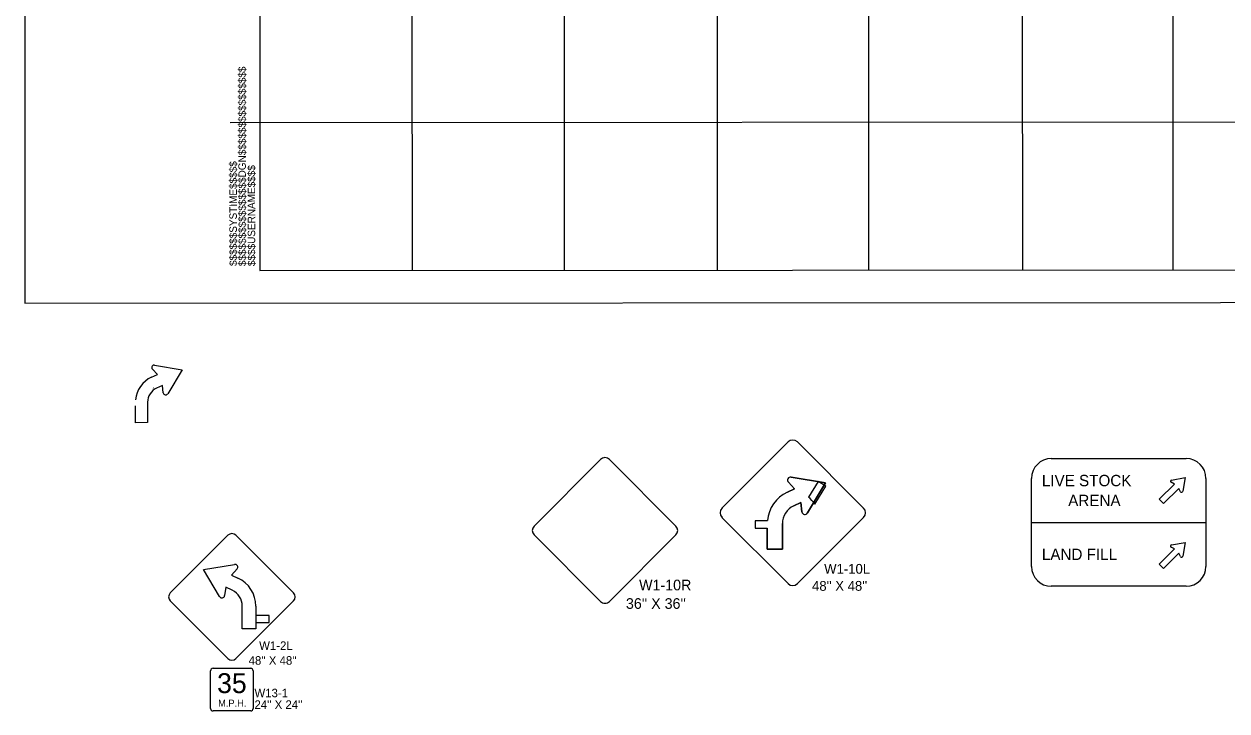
# Model space of a CAD drawing. Extents: x 1977705 to 1981198, y 827296 to 829291.
# Drawn here: x 1979337 to 1980184, y 827354 to 827837 of the extents above; entities that cross this region are included whole.
import ezdxf

# ---------------------------------------------------------------- set-up
doc = ezdxf.new("R2010")
doc.units = 0
for name, color, linetype in [('Default', 7, 'Continuous'), ('Level 19', 7, 'Continuous'), ('Level 22', 7, 'Continuous'), ('Level 23', 7, 'Continuous'), ('Level 3', 7, 'Continuous'), ('Level 34', 7, 'Continuous'), ('Level 5', 7, 'Continuous'), ('Level 7', 7, 'Continuous')]:
    doc.layers.add(name, color=color, linetype=linetype)

msp = doc.modelspace()

# ---------------------------------------------------------------- linework, layer by layer
at = {"layer": 'Default'}
for p, q in [((1979428.52, 827597.16), (1979447.93, 827593.88)), ((1979428.52, 827597.16), (1979428.52, 827597.16)), ((1979447.93, 827593.88), (1979437.81, 827576.99)), ((1979427.68, 827581.01), (1979427.66, 827581.03)), ((1979434.06, 827582.8), (1979429.99, 827580.94)), ((1979434.67, 827577.66), (1979434.06, 827582.8)), ((1979423.63, 827571), (1979423.63, 827556.62)), ((1979415.12, 827565.15), (1979415.12, 827568.47)), ((1979415.13, 827556.61), (1979415.12, 827565.15)), ((1979423.63, 827556.62), (1979415.13, 827556.61)), ((1979876.66, 827518.26), (1979876.66, 827518.25)), ((1979875.6, 827498.06), (1979875.58, 827498.09)), ((1979748.75, 827430.83), (1979795.6, 827477.68))]:
    msp.add_line(p, q, dxfattribs=at)
for points in [[(1979426.44, 827588.67), (1979430.5, 827590.52), (1979426.99, 827594.34)], [(1979742.56, 827530.71), (1979695.72, 827483.86)], [(1979795.6, 827483.86), (1979748.75, 827530.71)], [(1979695.72, 827477.68), (1979742.56, 827430.83)]]:
    msp.add_lwpolyline(points, dxfattribs=at)
for centre, radius, start, end in [((1979428.24, 827595.49), 1.7, 80.39954, 222.52148), ((1979434.57, 827571), 19.45, 114.72375, 175.10401), ((1979434.57, 827571), 10.94, 114.72375, 180.03077), ((1979436.36, 827577.86), 1.7, 186.91942, 329.04792), ((1979745.66, 827527.62), 4.38, 89.99348, 135), ((1979745.66, 827527.62), 4.38, 44.98697, 89.99348), ((1979698.81, 827480.77), 4.38, 135, 225), ((1979792.5, 827480.77), 4.38, 315, 45), ((1979745.66, 827433.92), 4.38, 225, 270), ((1979745.66, 827433.92), 4.38, 270, 315)]:
    msp.add_arc(centre, radius, start, end, dxfattribs=at)
at = {"layer": 'Level 19'}
for p, q in [((1979874.56, 827543.03), (1979828.03, 827496.5)), ((1979927.73, 827496.5), (1979881.2, 827543.03)), ((1979876.66, 827518.25), (1979876.66, 827518.26)), ((1979876.66, 827518.25), (1979876.66, 827518.26)), ((1979876.66, 827518.25), (1979900.92, 827514.16)), ((1979900.92, 827514.16), (1979876.66, 827518.25)), ((1979900.92, 827514.16), (1979876.66, 827518.25)), ((1979879.13, 827509.96), (1979874.05, 827507.64)), ((1979874.74, 827514.73), (1979879.13, 827509.96)), ((1979900.92, 827514.16), (1979888.27, 827493.04)), ((1979888.27, 827493.04), (1979900.92, 827514.16)), ((1979888.27, 827493.04), (1979900.92, 827514.16)), ((1979883.58, 827500.31), (1979878.5, 827497.98)), ((1979878.5, 827497.98), (1979883.58, 827500.31)), ((1979878.5, 827497.98), (1979883.58, 827500.31)), ((1979884.34, 827493.88), (1979883.58, 827500.31)), ((1979883.58, 827500.31), (1979884.34, 827493.88)), ((1979883.58, 827500.31), (1979884.34, 827493.88)), ((1979828.03, 827489.86), (1979874.56, 827443.34)), ((1979870.54, 827485.55), (1979870.55, 827467.58)), ((1979870.55, 827467.58), (1979870.54, 827485.55)), ((1979870.55, 827467.58), (1979870.54, 827485.55)), ((1979881.2, 827443.34), (1979927.73, 827489.86)), ((1979480.08, 827477.34), (1979439.62, 827436.87)), ((1979526.32, 827436.87), (1979485.85, 827477.34)), ((1979859.91, 827478.25), (1979859.91, 827482.39)), ((1979859.91, 827482.39), (1979859.91, 827478.25)), ((1979859.91, 827482.39), (1979859.91, 827478.25)), ((1979859.92, 827467.57), (1979859.91, 827478.25)), ((1979859.91, 827478.25), (1979859.92, 827467.57)), ((1979859.91, 827478.25), (1979859.92, 827467.57)), ((1979870.55, 827467.58), (1979859.92, 827467.57)), ((1979859.92, 827467.57), (1979870.55, 827467.58)), ((1979859.92, 827467.57), (1979870.55, 827467.58)), ((1979439.62, 827431.1), (1979480.08, 827390.63)), ((1979485.85, 827390.63), (1979526.32, 827431.1)), ((1979490.29, 827411.44), (1979490.29, 827427.5)), ((1979490.29, 827411.44), (1979490.29, 827427.5)), ((1979490.29, 827411.44), (1979490.29, 827427.5)), ((1979499.81, 827421), (1979499.8, 827416.05)), ((1979497.97, 827381.96), (1979497.97, 827355.46))]:
    msp.add_line(p, q, dxfattribs=at)
for points in [[(1979874.05, 827507.64), (1979879.13, 827509.96), (1979874.74, 827514.73)], [(1979874.74, 827514.73), (1979879.13, 827509.96), (1979874.05, 827507.64)], [(1979893.28, 827499.25), (1979901.05, 827511.91), (1979895.71, 827515.18), (1979889.02, 827504.27)], [(1979860, 827487.63), (1979851.39, 827487.63), (1979851.39, 827482.39), (1979859.91, 827482.39)], [(1979860, 827487.63), (1979851.39, 827487.63), (1979851.39, 827482.39), (1979859.91, 827482.39)], [(1979860, 827487.63), (1979851.39, 827487.63), (1979851.39, 827482.39), (1979859.91, 827482.39)], [(1979474.35, 827434.16), (1979463.08, 827453.21), (1979484.91, 827456.87)], [(1979474.35, 827434.16), (1979463.08, 827453.21), (1979484.91, 827456.87)], [(1979474.35, 827434.16), (1979463.08, 827453.21), (1979484.91, 827456.87)], [(1979486.63, 827453.7), (1979482.65, 827449.36), (1979487.22, 827447.23)], [(1979486.63, 827453.7), (1979482.65, 827449.36), (1979487.22, 827447.23)], [(1979486.63, 827453.7), (1979482.65, 827449.36), (1979487.22, 827447.23)], [(1979483.21, 827438.6), (1979478.63, 827440.72), (1979477.88, 827434.89)], [(1979483.21, 827438.6), (1979478.63, 827440.72), (1979477.88, 827434.89)], [(1979483.21, 827438.6), (1979478.63, 827440.72), (1979477.88, 827434.89)], [(1979499.81, 827427.5), (1979499.81, 827411.44), (1979490.29, 827411.44)], [(1979499.81, 827427.5), (1979499.81, 827411.44), (1979490.29, 827411.44)], [(1979499.81, 827427.5), (1979499.81, 827411.44), (1979490.29, 827411.44)], [(1979499.8, 827416.05), (1979509.17, 827416.05), (1979509.17, 827421), (1979499.81, 827421)], [(1979469.72, 827383.71), (1979482.97, 827383.71)], [(1979482.97, 827383.71), (1979496.22, 827383.71)], [(1979467.97, 827355.46), (1979467.97, 827381.96)], [(1979482.97, 827353.71), (1979469.72, 827353.71)], [(1979496.22, 827353.71), (1979482.97, 827353.71)]]:
    msp.add_lwpolyline(points, dxfattribs=at)
for centre, radius, start, end in [((1979877.88, 827539.71), 4.69, 45, 135), ((1979876.3, 827516.17), 2.12, 80.39954, 222.52148), ((1979876.3, 827516.17), 2.12, 80.39954, 222.52148), ((1979876.3, 827516.17), 2.12, 80.39954, 222.52148), ((1979884.22, 827485.56), 24.31, 114.72375, 175.10401), ((1979884.22, 827485.56), 24.31, 114.72375, 175.10401), ((1979884.22, 827485.56), 24.31, 114.72375, 175.10401), ((1979872.22, 827485.72), 25.03, 32.7091, 47.83665), ((1979831.35, 827493.18), 4.69, 135, 225), ((1979884.22, 827485.56), 13.68, 114.72375, 180.03077), ((1979884.22, 827485.56), 13.68, 114.72375, 180.03077), ((1979884.22, 827485.56), 13.68, 114.72375, 180.03077), ((1979886.45, 827494.13), 2.12, 186.91942, 329.04792), ((1979886.45, 827494.13), 2.12, 186.91942, 329.04792), ((1979886.45, 827494.13), 2.12, 186.91942, 329.04792), ((1979924.41, 827493.18), 4.69, 315, 45), ((1979482.97, 827474.45), 4.08, 45, 135), ((1979877.88, 827446.65), 4.69, 225, 315), ((1979442.5, 827433.99), 4.08, 135, 225), ((1979523.43, 827433.99), 4.08, 315, 45), ((1979469.72, 827381.96), 1.75, 89.98697, 180), ((1979482.97, 827393.52), 4.08, 225, 315), ((1979496.22, 827381.96), 1.75, 0, 90), ((1979469.72, 827355.46), 1.75, 180, 270), ((1979496.22, 827355.46), 1.75, 270, 360)]:
    msp.add_arc(centre, radius, start, end, dxfattribs=at)
for centre, major_axis, start_param, end_param in [((1979485.23, 827454.99), (0, 1.9), 3.969953, 6.449197), ((1979485.23, 827454.99), (0, 1.9), 3.969953, 6.449197), ((1979485.23, 827454.99), (0, 1.9), 3.969953, 6.449197), ((1979478.05, 827427.5), (0, 21.77), 4.712389, 5.847944), ((1979478.05, 827427.5), (0, 21.77), 4.712389, 5.847944), ((1979478.05, 827427.5), (0, 21.77), 4.712389, 5.847944), ((1979475.99, 827435.13), (0, -1.9), 5.246691, 7.725935), ((1979475.99, 827435.13), (0, -1.9), 5.246691, 7.725935), ((1979475.99, 827435.13), (0, -1.9), 5.246691, 7.725935), ((1979478.05, 827427.5), (0, 12.24), 4.712389, 5.847944), ((1979478.05, 827427.5), (0, 12.24), 4.712389, 5.847944), ((1979478.05, 827427.5), (0, 12.24), 4.712389, 5.847944)]:
    msp.add_ellipse(centre, major_axis=major_axis, ratio=0.999989, start_param=start_param, end_param=end_param, dxfattribs=at)
at = {"layer": 'Level 22'}
msp.add_line((1980045.96, 827486.4), (1980168.72, 827486.4), dxfattribs=at)
for points in [[(1980059.89, 827531.35), (1980154.79, 827531.35)], [(1980045.96, 827455.39), (1980045.96, 827517.42)], [(1980168.72, 827517.42), (1980168.72, 827455.39)], [(1980154.79, 827441.45), (1980059.89, 827441.45)]]:
    msp.add_lwpolyline(points, dxfattribs=at)
for centre, start, end in [((1980059.89, 827517.42), 90, 180), ((1980154.79, 827517.42), 0, 90), ((1980059.89, 827455.39), 180, 270), ((1980154.79, 827455.39), 270, 0)]:
    msp.add_arc(centre, 13.93, start, end, dxfattribs=at)
at = {"layer": 'Level 23'}
for points in [[(1980144.44, 827516.24), (1980154.22, 827518.06), (1980152.39, 827508.28)], [(1980144.44, 827516.24), (1980154.22, 827518.06), (1980152.39, 827508.28)], [(1980144.44, 827516.24), (1980154.22, 827518.06), (1980152.39, 827508.28)], [(1980150.79, 827508.04), (1980149.57, 827510.39), (1980138.87, 827499.69), (1980135.84, 827502.71), (1980146.55, 827513.42), (1980144.2, 827514.63)], [(1980150.79, 827508.04), (1980149.57, 827510.39), (1980138.87, 827499.69), (1980135.84, 827502.71), (1980146.55, 827513.42), (1980144.2, 827514.63)], [(1980150.79, 827508.04), (1980149.57, 827510.39), (1980138.87, 827499.69), (1980135.84, 827502.71), (1980146.55, 827513.42), (1980144.2, 827514.63)], [(1980150.79, 827462.34), (1980149.57, 827464.69), (1980138.87, 827453.99), (1980135.84, 827457.01), (1980146.55, 827467.72), (1980144.2, 827468.94)], [(1980150.79, 827462.34), (1980149.57, 827464.69), (1980138.87, 827453.99), (1980135.84, 827457.01), (1980146.55, 827467.72), (1980144.2, 827468.94)], [(1980150.79, 827462.34), (1980149.57, 827464.69), (1980138.87, 827453.99), (1980135.84, 827457.01), (1980146.55, 827467.72), (1980144.2, 827468.94)], [(1980144.44, 827470.54), (1980154.22, 827472.36), (1980152.39, 827462.58)], [(1980144.44, 827470.54), (1980154.22, 827472.36), (1980152.39, 827462.58)], [(1980144.44, 827470.54), (1980154.22, 827472.36), (1980152.39, 827462.58)]]:
    msp.add_lwpolyline(points, dxfattribs=at)
for centre, start, end in [((1980144.59, 827515.39), 100.55076, 242.60096), ((1980144.59, 827515.39), 100.55076, 242.60096), ((1980144.59, 827515.39), 100.55076, 242.60096), ((1980151.55, 827508.43), 207.39904, 349.44924), ((1980151.55, 827508.43), 207.39904, 349.44924), ((1980151.55, 827508.43), 207.39904, 349.44924), ((1980144.59, 827469.7), 100.55076, 242.60096), ((1980144.59, 827469.7), 100.55076, 242.60096), ((1980144.59, 827469.7), 100.55076, 242.60096), ((1980151.55, 827462.74), 207.39904, 349.44924), ((1980151.55, 827462.74), 207.39904, 349.44924), ((1980151.55, 827462.74), 207.39904, 349.44924)]:
    msp.add_arc(centre, 0.856, start, end, dxfattribs=at)
at = {"layer": 'Level 3'}
msp.add_lwpolyline([(1981020.16, 828736.58), (1979336.66, 828735.68), (1979337.25, 827640.68), (1981020.75, 827641.58)], close=True, dxfattribs=at)
at = {"layer": 'Level 34'}
for p, q in [((1979610.04, 827663.85), (1979609.44, 828783.03)), ((1979824.92, 827663.96), (1979824.32, 828783.14)), ((1980039.8, 827664.08), (1980039.2, 828783.26)), ((1981002.3, 827768.54), (1979481.66, 827767.72))]:
    msp.add_line(p, q, dxfattribs=at)
at = {"layer": 'Level 7'}
msp.add_lwpolyline([(1981001.8, 828714.37), (1979502.12, 828713.56), (1979502.69, 827663.79), (1981002.36, 827664.6)], close=True, dxfattribs=at)
for points in [[(1979716.94, 828713.68), (1979716.94, 827663.9)], [(1979931.19, 828713.79), (1979931.19, 827664.02)], [(1980145.44, 828713.91), (1980145.44, 827664.13)]]:
    msp.add_lwpolyline(points, dxfattribs=at)

# ---------------------------------------------------------------- texts
at = {"layer": 'Default'}
for s, height, p in [('W1-10L', 6.899, (1979899.97, 827450.28)), ('W1-10R', 7.5, (1979769.67, 827438.59)), ("48'' X 48''", 6.8989, (1979891.44, 827438.29)), ("36'' X 36''", 7.5002, (1979760.4, 827425.56)), ('W1-2L', 6, (1979502.18, 827396.68)), ("48'' X 48''", 6, (1979494.76, 827386.25)), ('35', 14, (1979472.57, 827366.27)), ('W13-1', 6, (1979498.88, 827363.32)), ('M.P.H.', 4.86, (1979473.31, 827356.75)), ("24'' X 24''", 6, (1979498.88, 827355.17))]:
    msp.add_text(s, height=height, dxfattribs=at).set_placement(p)
at = {"layer": 'Level 22'}
for s, p in [('LIVE STOCK', (1980053.25, 827511.88)), ('ARENA', (1980071.78, 827497.88)), ('LAND FILL', (1980053.25, 827459.93))]:
    msp.add_text(s, height=8, dxfattribs=at).set_placement(p)
at = {"layer": 'Level 5'}
for s, p in [('$$$$$$$$$$$$$$$$DGN$$$$$$$$$$$$$$$$', (1979492.84, 827666.78)), ('$$$$$$SYSTIME$$$$$', (1979486.49, 827666.88)), ('$$$$USERNAME$$$$', (1979499.39, 827666.84))]:
    msp.add_text(s, height=5.2488, rotation=90.0308, dxfattribs=at).set_placement(p)

doc.saveas('drawing.dxf')
